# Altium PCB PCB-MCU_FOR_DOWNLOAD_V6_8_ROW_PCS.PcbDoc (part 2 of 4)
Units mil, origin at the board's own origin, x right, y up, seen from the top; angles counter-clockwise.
Board outline not stored, 4 copper layers (Top, GND1, GND2, Bottom), stack 35.4 mil thick; 280 components, 38 nets, 1144 pads, 944 vias.
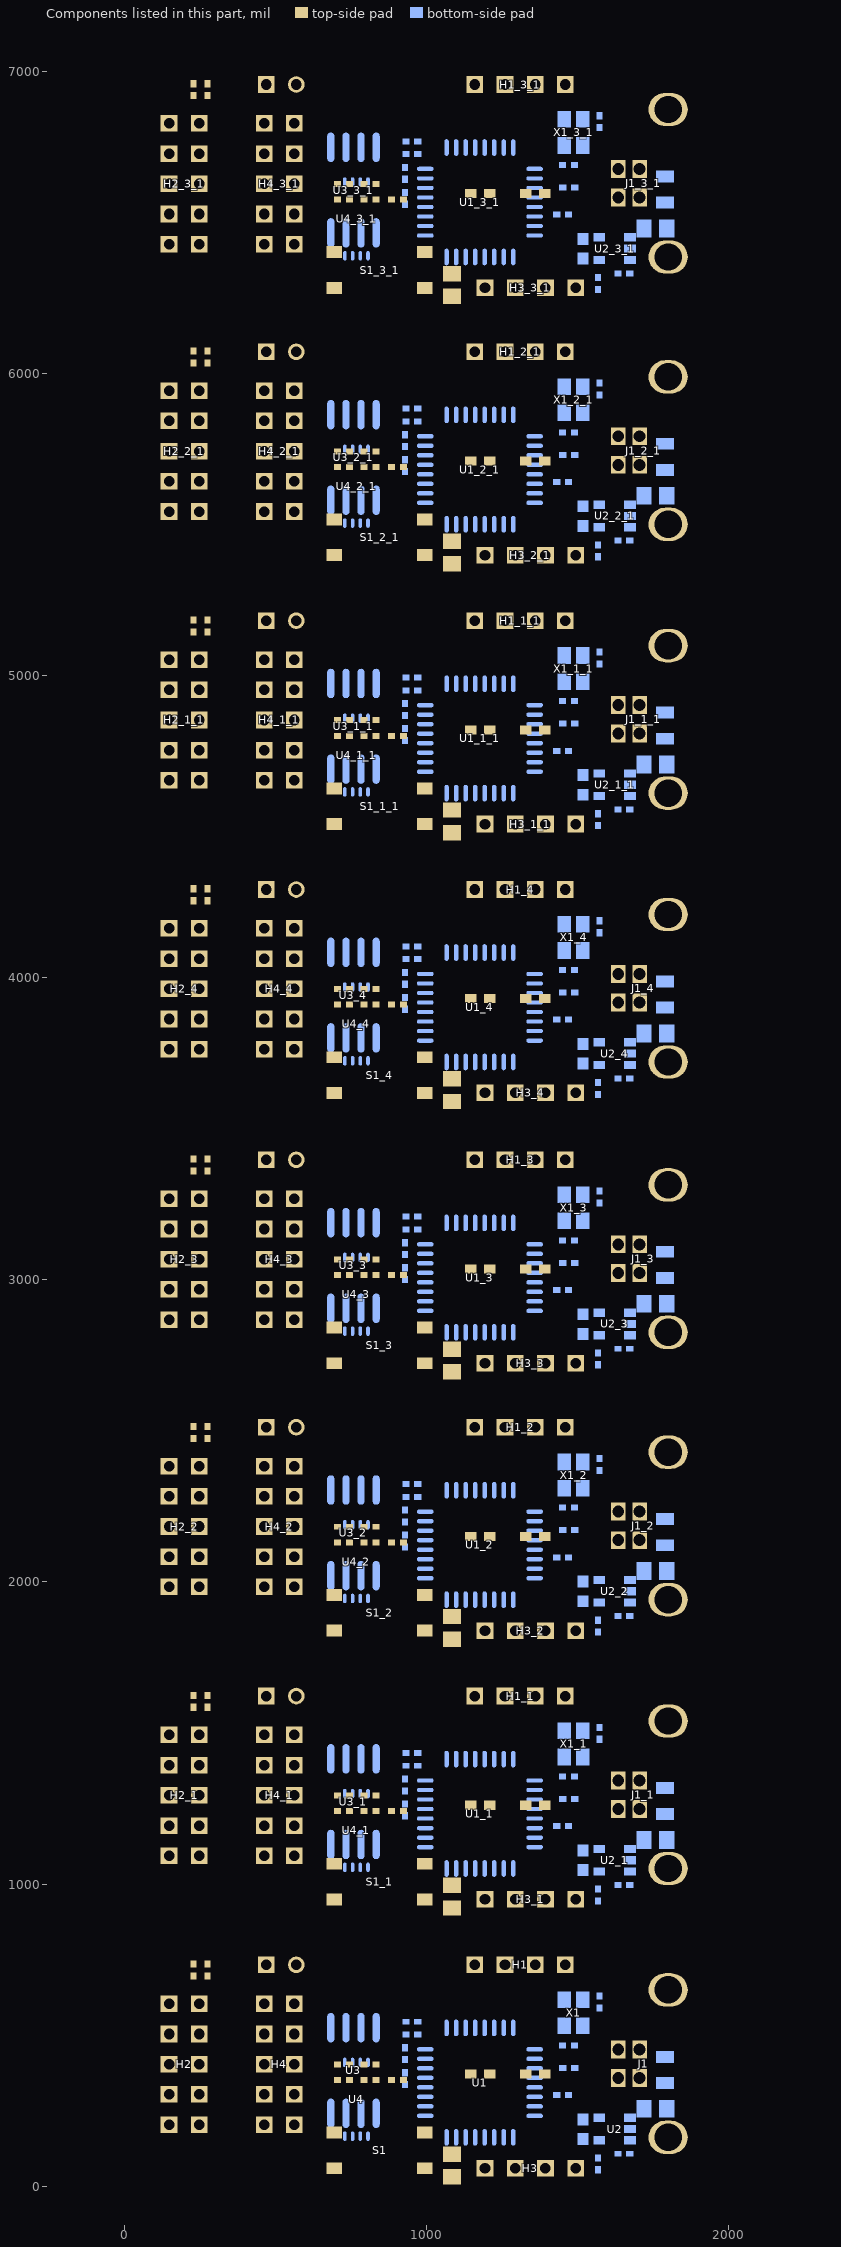
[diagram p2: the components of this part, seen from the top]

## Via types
v1: diameter 16/16/16/16 (per signal layer), hole 8, Top to Bottom, 936 vias
v2: diameter 55/55/55/55 (per signal layer), hole 37, Top to Bottom, 8 vias

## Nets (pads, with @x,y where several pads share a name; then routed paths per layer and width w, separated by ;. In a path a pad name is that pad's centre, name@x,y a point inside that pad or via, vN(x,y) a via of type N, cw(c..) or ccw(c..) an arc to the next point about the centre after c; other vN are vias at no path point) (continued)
copper on no net: | length 208596.2
  Top w7.87: v1(41.34,1641.97) 79.53,1680.16 644.09,1680.16 648.03,1676.22 v1(648.03,1673.07) ; v1(41.34,2531.97) 79.53,2570.16 644.09,2570.16 648.03,2566.22 v1(648.03,2563.07) ; v1(41.34,3416.97) 79.53,3455.16 644.09,3455.16 648.03,3451.22 v1(648.03,3448.07) ; v1(41.34,4311.97) 79.53,4350.16 644.09,4350.16 648.03,4346.22 v1(648.03,4343.07) ; v1(41.34,5201.97) 79.53,5240.16 644.09,5240.16 648.03,5236.22 v1(648.03,5233.07) ; v1(41.34,6091.97) 79.53,6130.16 644.09,6130.16 648.03,6126.22 v1(648.03,6123.07) ; v1(41.34,6976.97) 79.53,7015.16 644.09,7015.16 648.03,7011.22 v1(648.03,7008.07) ; 67.32,1585.28 69.69,1585.28 ; 67.32,2475.28 69.69,2475.28 ; 67.32,3360.28 69.69,3360.28 ; 67.32,4255.28 69.69,4255.28 ; 67.32,5145.28 69.69,5145.28 ; 67.32,6035.28 69.69,6035.28 ; 67.32,6920.28 69.69,6920.28 ; 146.85,1093.54 194.88,1141.57 329.92,1141.57 422.44,1049.06 594.49,1049.06 656.3,1110.87 1048.03,1110.87 v1(1074.41,1084.49) ; 146.85,1193.54 146.85,1194.72 192.52,1240.39 322.34,1240.39 409.45,1153.29 605.02,1153.29 617.32,1140.98 1081.69,1140.98 v1(1127.95,1094.72) ; 146.85,1493.54 149.2,1493.54 203.54,1439.2 203.54,1437.24 292.52,1437.24 314.57,1415.2 314.57,1344.33 425.59,1233.31 597.05,1233.31 674.8,1155.55 1155.71,1155.55 v1(1222.44,1088.82) ; 146.85,1983.54 194.88,2031.57 329.92,2031.57 422.44,1939.06 594.49,1939.06 656.3,2000.87 1048.03,2000.87 v1(1074.41,1974.49) ; 146.85,2083.54 146.85,2084.72 192.52,2130.39 322.34,2130.39 409.45,2043.29 605.02,2043.29 617.32,2030.98 1081.69,2030.98 v1(1127.95,1984.72) ; 146.85,2383.54 149.2,2383.54 203.54,2329.2 203.54,2327.24 292.52,2327.24 314.57,2305.2 314.57,2234.33 425.59,2123.31 597.05,2123.31 674.8,2045.55 1155.71,2045.55 v1(1222.44,1978.82) ; 146.85,2868.54 194.88,2916.57 329.92,2916.57 422.44,2824.06 594.49,2824.06 656.3,2885.87 1048.03,2885.87 v1(1074.41,2859.49) ; 146.85,2968.54 146.85,2969.72 192.52,3015.39 322.34,3015.39 409.45,2928.29 605.02,2928.29 617.32,2915.98 1081.69,2915.98 v1(1127.95,2869.72) ; 146.85,3268.54 149.2,3268.54 203.54,3214.2 203.54,3212.24 292.52,3212.24 314.57,3190.2 314.57,3119.33 425.59,3008.31 597.05,3008.31 674.8,2930.55 1155.71,2930.55 v1(1222.44,2863.82) ; 146.85,3763.54 194.88,3811.57 329.92,3811.57 422.44,3719.06 594.49,3719.06 656.3,3780.87 1048.03,3780.87 v1(1074.41,3754.49) ; 146.85,3863.54 146.85,3864.72 192.52,3910.39 322.34,3910.39 409.45,3823.29 605.02,3823.29 617.32,3810.98 1081.69,3810.98 v1(1127.95,3764.72) ; 146.85,4163.54 149.2,4163.54 203.54,4109.2 203.54,4107.24 292.52,4107.24 314.57,4085.2 314.57,4014.33 425.59,3903.31 597.05,3903.31 674.8,3825.55 1155.71,3825.55 v1(1222.44,3758.82) ; 146.85,4653.54 194.88,4701.57 329.92,4701.57 422.44,4609.06 594.49,4609.06 656.3,4670.87 1048.03,4670.87 v1(1074.41,4644.49) ; 146.85,4753.54 146.85,4754.72 192.52,4800.39 322.34,4800.39 409.45,4713.29 605.02,4713.29 617.32,4700.98 1081.69,4700.98 v1(1127.95,4654.72) ; 146.85,5053.54 149.2,5053.54 203.54,4999.2 203.54,4997.24 292.52,4997.24 314.57,4975.2 314.57,4904.33 425.59,4793.31 597.05,4793.31 674.8,4715.55 1155.71,4715.55 v1(1222.44,4648.82) ; 146.85,5543.54 194.88,5591.57 329.92,5591.57 422.44,5499.06 594.49,5499.06 656.3,5560.87 1048.03,5560.87 v1(1074.41,5534.49) ; 146.85,5643.54 146.85,5644.72 192.52,5690.39 322.34,5690.39 409.45,5603.29 605.02,5603.29 617.32,5590.98 1081.69,5590.98 v1(1127.95,5544.72) ; 146.85,5943.54 149.2,5943.54 203.54,5889.2 203.54,5887.24 292.52,5887.24 314.57,5865.2 314.57,5794.33 425.59,5683.31 597.05,5683.31 674.8,5605.55 1155.71,5605.55 v1(1222.44,5538.82) ; 146.85,6428.54 194.88,6476.57 329.92,6476.57 422.44,6384.06 594.49,6384.06 656.3,6445.87 1048.03,6445.87 v1(1074.41,6419.49) ; 146.85,6528.54 146.85,6529.72 192.52,6575.39 322.34,6575.39 409.45,6488.29 605.02,6488.29 617.32,6475.98 1081.69,6475.98 v1(1127.95,6429.72) ; 146.85,6828.54 149.2,6828.54 203.54,6774.2 203.54,6772.24 292.52,6772.24 314.57,6750.2 314.57,6679.33 425.59,6568.31 597.05,6568.31 674.8,6490.55 1155.71,6490.55 v1(1222.44,6423.82) ; v1(196.85,1054.96) 202.76,1054.96 238.58,1019.13 622.83,1019.13 v1@648.83,1045.13 ; v1(196.85,1944.96) 202.76,1944.96 238.58,1909.13 622.83,1909.13 v1@648.83,1935.13 ; v1(196.85,2829.96) 202.76,2829.96 238.58,2794.13 622.83,2794.13 v1@648.83,2820.13 ; v1(196.85,3724.96) 202.76,3724.96 238.58,3689.13 622.83,3689.13 v1@648.83,3715.13 ; v1(196.85,4614.96) 202.76,4614.96 238.58,4579.13 622.83,4579.13 v1@648.83,4605.13 ; v1(196.85,5504.96) 202.76,5504.96 238.58,5469.13 622.83,5469.13 v1@648.83,5495.13 ; v1(196.85,6389.96) 202.76,6389.96 238.58,6354.13 622.83,6354.13 v1@648.83,6380.13 ; 227.95,1624.65 274.02,1624.65 251.18,1601.81 251.18,1501.02 246.85,1496.69 246.85,1493.54 ; 227.95,2514.65 274.02,2514.65 251.18,2491.81 251.18,2391.02 246.85,2386.69 246.85,2383.54 ; 227.95,3399.65 274.02,3399.65 251.18,3376.81 251.18,3276.02 246.85,3271.69 246.85,3268.54 ; 227.95,4294.65 274.02,4294.65 251.18,4271.81 251.18,4171.02 246.85,4166.69 246.85,4163.54 ; 227.95,5184.65 274.02,5184.65 251.18,5161.81 251.18,5061.02 246.85,5056.69 246.85,5053.54 ; 227.95,6074.65 274.02,6074.65 251.18,6051.81 251.18,5951.02 246.85,5946.69 246.85,5943.54 ; 227.95,6959.65 274.02,6959.65 251.18,6936.81 251.18,6836.02 246.85,6831.69 246.85,6828.54 ; 246.85,1093.54 251.68,1093.54 255.02,1090.2 257.58,1090.2 314.17,1033.6 600.39,1033.6 663.78,1096.99 1025.89,1096.99 1059.65,1063.23 1135.33,1063.23 1156.59,1084.49 1156.99,1084.49 1156.99,1088.33 v1(1159.45,1090.79) ; 246.85,1193.54 327.17,1193.54 327.36,1193.74 385.83,1135.28 599.21,1135.28 609.06,1125.43 1063.78,1125.43 v1(1096.46,1092.76) ; 246.85,1983.54 251.68,1983.54 255.02,1980.2 257.58,1980.2 314.17,1923.6 600.39,1923.6 663.78,1986.99 1025.89,1986.99 1059.65,1953.23 1135.33,1953.23 1156.59,1974.49 1156.99,1974.49 1156.99,1978.33 v1(1159.45,1980.79) ; 246.85,2083.54 327.17,2083.54 327.36,2083.74 385.83,2025.28 599.21,2025.28 609.06,2015.43 1063.78,2015.43 v1(1096.46,1982.76) ; 246.85,2868.54 251.68,2868.54 255.02,2865.2 257.58,2865.2 314.17,2808.6 600.39,2808.6 663.78,2871.99 1025.89,2871.99 1059.65,2838.23 1135.33,2838.23 1156.59,2859.49 1156.99,2859.49 1156.99,2863.33 v1(1159.45,2865.79) ; 246.85,2968.54 327.17,2968.54 327.36,2968.74 385.83,2910.28 599.21,2910.28 609.06,2900.43 1063.78,2900.43 v1(1096.46,2867.76) ; 246.85,3763.54 251.68,3763.54 255.02,3760.2 257.58,3760.2 314.17,3703.6 600.39,3703.6 663.78,3766.99 1025.89,3766.99 1059.65,3733.23 1135.33,3733.23 1156.59,3754.49 1156.99,3754.49 1156.99,3758.33 v1(1159.45,3760.79) ; 246.85,3863.54 327.17,3863.54 327.36,3863.74 385.83,3805.28 599.21,3805.28 609.06,3795.43 1063.78,3795.43 v1(1096.46,3762.76) ; 246.85,4653.54 251.68,4653.54 255.02,4650.2 257.58,4650.2 314.17,4593.6 600.39,4593.6 663.78,4656.99 1025.89,4656.99 1059.65,4623.23 1135.33,4623.23 1156.59,4644.49 1156.99,4644.49 1156.99,4648.33 v1(1159.45,4650.79) ; 246.85,4753.54 327.17,4753.54 327.36,4753.74 385.83,4695.28 599.21,4695.28 609.06,4685.43 1063.78,4685.43 v1(1096.46,4652.76) ; 246.85,5543.54 251.68,5543.54 255.02,5540.2 257.58,5540.2 314.17,5483.6 600.39,5483.6 663.78,5546.99 1025.89,5546.99 1059.65,5513.23 1135.33,5513.23 1156.59,5534.49 1156.99,5534.49 1156.99,5538.33 v1(1159.45,5540.79) ; 246.85,5643.54 327.17,5643.54 327.36,5643.74 385.83,5585.28 599.21,5585.28 609.06,5575.43 1063.78,5575.43 v1(1096.46,5542.76) ; 246.85,6428.54 251.68,6428.54 255.02,6425.2 257.58,6425.2 314.17,6368.6 600.39,6368.6 663.78,6431.99 1025.89,6431.99 1059.65,6398.23 1135.33,6398.23 1156.59,6419.49 1156.99,6419.49 1156.99,6423.33 v1(1159.45,6425.79) ; 246.85,6528.54 327.17,6528.54 327.36,6528.74 385.83,6470.28 599.21,6470.28 609.06,6460.43 1063.78,6460.43 v1(1096.46,6427.76) ; 274.02,1585.28 316.14,1585.28 381.89,1519.53 381.89,1374.25 411.42,1344.72 v1(600.39,1344.72) 701.97,1243.15 701.97,1241.18 701.97,1232.52 706.5,1227.99 ; 274.02,2475.28 316.14,2475.28 381.89,2409.53 381.89,2264.25 411.42,2234.72 v1(600.39,2234.72) 701.97,2133.15 701.97,2131.18 701.97,2122.52 706.5,2117.99 ; 274.02,3360.28 316.14,3360.28 381.89,3294.53 381.89,3149.25 411.42,3119.72 v1(600.39,3119.72) 701.97,3018.15 701.97,3016.18 701.97,3007.52 706.5,3002.99 ; 274.02,4255.28 316.14,4255.28 381.89,4189.53 381.89,4044.25 411.42,4014.72 v1(600.39,4014.72) 701.97,3913.15 701.97,3911.18 701.97,3902.52 706.5,3897.99 ; 274.02,5145.28 316.14,5145.28 381.89,5079.53 381.89,4934.25 411.42,4904.72 v1(600.39,4904.72) 701.97,4803.15 701.97,4801.18 701.97,4792.52 706.5,4787.99 ; 274.02,6035.28 316.14,6035.28 381.89,5969.53 381.89,5824.25 411.42,5794.72 v1(600.39,5794.72) 701.97,5693.15 701.97,5691.18 701.97,5682.52 706.5,5677.99 ; 274.02,6920.28 316.14,6920.28 381.89,6854.53 381.89,6709.25 411.42,6679.72 v1(600.39,6679.72) 701.97,6578.15 701.97,6576.18 701.97,6567.52 706.5,6562.99 ; 461.81,1493.54 460.63,1493.54 458.27,1491.18 458.86,1490.59 497.24,1452.2 759.45,1452.2 826.77,1384.88 869.29,1384.88 v1(872.05,1382.13) ; 461.81,2383.54 460.63,2383.54 458.27,2381.18 458.86,2380.59 497.24,2342.2 759.45,2342.2 826.77,2274.88 869.29,2274.88 v1(872.05,2272.13) ; 461.81,3268.54 460.63,3268.54 458.27,3266.18 458.86,3265.59 497.24,3227.2 759.45,3227.2 826.77,3159.88 869.29,3159.88 v1(872.05,3157.13) ; 461.81,4163.54 460.63,4163.54 458.27,4161.18 458.86,4160.59 497.24,4122.2 759.45,4122.2 826.77,4054.88 869.29,4054.88 v1(872.05,4052.13) ; 461.81,5053.54 460.63,5053.54 458.27,5051.18 458.86,5050.59 497.24,5012.2 759.45,5012.2 826.77,4944.88 869.29,4944.88 v1(872.05,4942.13) ; 461.81,5943.54 460.63,5943.54 458.27,5941.18 458.86,5940.59 497.24,5902.2 759.45,5902.2 826.77,5834.88 869.29,5834.88 v1(872.05,5832.13) ; 461.81,6828.54 460.63,6828.54 458.27,6826.18 458.86,6825.59 497.24,6787.2 759.45,6787.2 826.77,6719.88 869.29,6719.88 v1(872.05,6717.13) ; v1(692.91,1187.24) 693.31,1187.24 710.63,1169.92 1176.77,1169.92 v1(1185.04,1161.65) ; v1(692.91,1360.47) v1(1149.61,1360.47) ; v1(692.91,2077.24) 693.31,2077.24 710.63,2059.92 1176.77,2059.92 v1(1185.04,2051.65) ; v1(692.91,2250.47) v1(1149.61,2250.47) ; v1(692.91,2962.24) 693.31,2962.24 710.63,2944.92 1176.77,2944.92 v1(1185.04,2936.65) ; v1(692.91,3135.47) v1(1149.61,3135.47) ; v1(692.91,3857.24) 693.31,3857.24 710.63,3839.92 1176.77,3839.92 v1(1185.04,3831.65) ; v1(692.91,4030.47) v1(1149.61,4030.47) ; v1(692.91,4747.24) 693.31,4747.24 710.63,4729.92 1176.77,4729.92 v1(1185.04,4721.65) ; v1(692.91,4920.47) v1(1149.61,4920.47) ; v1(692.91,5637.24) 693.31,5637.24 710.63,5619.92 1176.77,5619.92 v1(1185.04,5611.65) ; v1(692.91,5810.47) v1(1149.61,5810.47) ; v1(692.91,6522.24) 693.31,6522.24 710.63,6504.92 1176.77,6504.92 v1(1185.04,6496.65) ; v1(692.91,6695.47) v1(1149.61,6695.47) ; 704.72,1241.18 706.5,1239.41 706.5,1227.99 ; 704.72,1292.76 704.72,1320.31 725.2,1340.79 874.8,1340.79 ; 704.72,2131.18 706.5,2129.41 706.5,2117.99 ; 704.72,2182.76 704.72,2210.31 725.2,2230.79 874.8,2230.79 ; 704.72,3016.18 706.5,3014.41 706.5,3002.99 ; 704.72,3067.76 704.72,3095.31 725.2,3115.79 874.8,3115.79 ; 704.72,3911.18 706.5,3909.41 706.5,3897.99 ; 704.72,3962.76 704.72,3990.31 725.2,4010.79 874.8,4010.79 ; 704.72,4801.18 706.5,4799.41 706.5,4787.99 ; 704.72,4852.76 704.72,4880.31 725.2,4900.79 874.8,4900.79 ; 704.72,5691.18 706.5,5689.41 706.5,5677.99 ; 704.72,5742.76 704.72,5770.31 725.2,5790.79 874.8,5790.79 ; 704.72,6576.18 706.5,6574.41 706.5,6562.99 ; 704.72,6627.76 704.72,6655.31 725.2,6675.79 874.8,6675.79 ; 744.09,1241.18 744.09,1292.76 744.09,1313.62 751.18,1320.71 753.54,1320.71 v1(753.94,1321.1) ; 744.09,2131.18 744.09,2182.76 744.09,2203.62 751.18,2210.71 753.54,2210.71 v1(753.94,2211.1) ; 744.09,3016.18 744.09,3067.76 744.09,3088.62 751.18,3095.71 753.54,3095.71 v1(753.94,3096.1) ; 744.09,3911.18 744.09,3962.76 744.09,3983.62 751.18,3990.71 753.54,3990.71 v1(753.94,3991.1) ; 744.09,4801.18 744.09,4852.76 744.09,4873.62 751.18,4880.71 753.54,4880.71 v1(753.94,4881.1) ; 744.09,5691.18 744.09,5742.76 744.09,5763.62 751.18,5770.71 753.54,5770.71 v1(753.94,5771.1) ; 744.09,6576.18 744.09,6627.76 744.09,6648.62 751.18,6655.71 753.54,6655.71 v1(753.94,6656.1) ; v1(783.46,1321.1) 803.15,1321.1 831.5,1292.76 ; v1(783.46,2211.1) 803.15,2211.1 831.5,2182.76 ; v1(783.46,3096.1) 803.15,3096.1 831.5,3067.76 ; v1(783.46,3991.1) 803.15,3991.1 831.5,3962.76 ; v1(783.46,4881.1) 803.15,4881.1 831.5,4852.76 ; v1(783.46,5771.1) 803.15,5771.1 831.5,5742.76 ; v1(783.46,6656.1) 803.15,6656.1 831.5,6627.76 ; v1(791.34,1210.87) 795.67,1206.54 795.67,1206.34 1225.2,1206.34 1261.42,1242.56 1261.42,1295.12 v1(1309.06,1342.76) ; v1(791.34,2100.87) 795.67,2096.54 795.67,2096.34 1225.2,2096.34 1261.42,2132.56 1261.42,2185.12 v1(1309.06,2232.76) ; v1(791.34,2985.87) 795.67,2981.54 795.67,2981.34 1225.2,2981.34 1261.42,3017.56 1261.42,3070.12 v1(1309.06,3117.76) ; v1(791.34,3880.87) 795.67,3876.54 795.67,3876.34 1225.2,3876.34 1261.42,3912.56 1261.42,3965.12 v1(1309.06,4012.76) ; v1(791.34,4770.87) 795.67,4766.54 795.67,4766.34 1225.2,4766.34 1261.42,4802.56 1261.42,4855.12 v1(1309.06,4902.76) ; v1(791.34,5660.87) 795.67,5656.54 795.67,5656.34 1225.2,5656.34 1261.42,5692.56 1261.42,5745.12 v1(1309.06,5792.76) ; v1(791.34,6545.87) 795.67,6541.54 795.67,6541.34 1225.2,6541.34 1261.42,6577.56 1261.42,6630.12 v1(1309.06,6677.76) ; 792.13,1241.18 792.13,1242.76 828.74,1279.37 828.74,1291.22 829.12,1291.59 829.12,1291.95 ; 792.13,1292.76 790.55,1292.76 767.5,1269.7 767.5,1240.79 767.13,1191.57 766.54,1188.43 ; 792.13,2131.18 792.13,2132.76 828.74,2169.37 828.74,2181.22 829.12,2181.59 829.12,2181.95 ; 792.13,2182.76 790.55,2182.76 767.5,2159.7 767.5,2130.79 767.13,2081.57 766.54,2078.43 ; 792.13,3016.18 792.13,3017.76 828.74,3054.37 828.74,3066.22 829.12,3066.59 829.12,3066.95 ; 792.13,3067.76 790.55,3067.76 767.5,3044.7 767.5,3015.79 767.13,2966.57 766.54,2963.43 ; 792.13,3911.18 792.13,3912.76 828.74,3949.37 828.74,3961.22 829.12,3961.59 829.12,3961.95 ; 792.13,3962.76 790.55,3962.76 767.5,3939.7 767.5,3910.79 767.13,3861.57 766.54,3858.43 ; 792.13,4801.18 792.13,4802.76 828.74,4839.37 828.74,4851.22 829.12,4851.59 829.12,4851.95 ; 792.13,4852.76 790.55,4852.76 767.5,4829.7 767.5,4800.79 767.13,4751.57 766.54,4748.43 ; 792.13,5691.18 792.13,5692.76 828.74,5729.37 828.74,5741.22 829.12,5741.59 829.12,5741.95 ; 792.13,5742.76 790.55,5742.76 767.5,5719.7 767.5,5690.79 767.13,5641.57 766.54,5638.43 ; 792.13,6576.18 792.13,6577.76 828.74,6614.37 828.74,6626.22 829.12,6626.59 829.12,6626.95 ; 792.13,6627.76 790.55,6627.76 767.5,6604.7 767.5,6575.79 767.13,6526.57 766.54,6523.43 ; 831.5,1241.18 832.28,1240.39 832.28,1238.03 838.39,1231.93 838.39,1230.75 v1(844.49,1224.65) ; 831.5,2131.18 832.28,2130.39 832.28,2128.03 838.39,2121.93 838.39,2120.75 v1(844.49,2114.65) ; 831.5,3016.18 832.28,3015.39 832.28,3013.03 838.39,3006.93 838.39,3005.75 v1(844.49,2999.65) ; 831.5,3911.18 832.28,3910.39 832.28,3908.03 838.39,3901.93 838.39,3900.75 v1(844.49,3894.65) ; 831.5,4801.18 832.28,4800.39 832.28,4798.03 838.39,4791.93 838.39,4790.75 v1(844.49,4784.65) ; 831.5,5691.18 832.28,5690.39 832.28,5688.03 838.39,5681.93 838.39,5680.75 v1(844.49,5674.65) ; 831.5,6576.18 832.28,6575.39 832.28,6573.03 838.39,6566.93 838.39,6565.75 v1(844.49,6559.65) ; 874.8,1241.57 874.8,1340.79 ; 874.8,2131.57 874.8,2230.79 ; 874.8,3016.57 874.8,3115.79 ; 874.8,3911.57 874.8,4010.79 ; 874.8,4801.57 874.8,4900.79 ; 874.8,5691.57 874.8,5790.79 ; 874.8,6576.57 874.8,6675.79 ; v1(893.7,1269.92) 922.44,1241.18 ; v1(893.7,2159.92) 922.44,2131.18 ; v1(893.7,3044.92) 922.44,3016.18 ; v1(893.7,3939.92) 922.44,3911.18 ; v1(893.7,4829.92) 922.44,4801.18 ; v1(893.7,5719.92) 922.44,5691.18 ; v1(893.7,6604.92) 922.44,6576.18 ; v1(944.88,1069.13) 991.34,1069.13 993.31,1067.17 ; v1(944.88,1959.13) 991.34,1959.13 993.31,1957.17 ; v1(944.88,2844.13) 991.34,2844.13 993.31,2842.17 ; v1(944.88,3739.13) 991.34,3739.13 993.31,3737.17 ; v1(944.88,4629.13) 991.34,4629.13 993.31,4627.17 ; v1(944.88,5519.13) 991.34,5519.13 993.31,5517.17 ; v1(944.88,6404.13) 991.34,6404.13 993.31,6402.17 ; v1(948.82,1265.98) 1143.31,1265.98 1146.17,1263.13 1146.17,1260.87 ; v1(948.82,2155.98) 1143.31,2155.98 1146.17,2153.13 1146.17,2150.87 ; v1(948.82,3040.98) 1143.31,3040.98 1146.17,3038.13 1146.17,3035.87 ; v1(948.82,3935.98) 1143.31,3935.98 1146.17,3933.13 1146.17,3930.87 ; v1(948.82,4825.98) 1143.31,4825.98 1146.17,4823.13 1146.17,4820.87 ; v1(948.82,5715.98) 1143.31,5715.98 1146.17,5713.13 1146.17,5710.87 ; v1(948.82,6600.98) 1143.31,6600.98 1146.17,6598.13 1146.17,6595.87 ; v1(1191.73,1378.98) 1192.52,1378.19 1192.52,1372.68 1160.63,1340.79 874.8,1340.79 ; v1(1191.73,2268.98) 1192.52,2268.19 1192.52,2262.68 1160.63,2230.79 874.8,2230.79 ; v1(1191.73,3153.98) 1192.52,3153.19 1192.52,3147.68 1160.63,3115.79 874.8,3115.79 ; v1(1191.73,4048.98) 1192.52,4048.19 1192.52,4042.68 1160.63,4010.79 874.8,4010.79 ; v1(1191.73,4938.98) 1192.52,4938.19 1192.52,4932.68 1160.63,4900.79 874.8,4900.79 ; v1(1191.73,5828.98) 1192.52,5828.19 1192.52,5822.68 1160.63,5790.79 874.8,5790.79 ; v1(1191.73,6713.98) 1192.52,6713.19 1192.52,6707.68 1160.63,6675.79 874.8,6675.79 ; v1(1222.44,1122.28) 1223.62,1123.46 1283.86,1123.46 1309.65,1097.68 1583.27,1097.68 1639.76,1041.18 1640.16,1041.57 v1(1702.76,1041.57) ; v1(1222.44,2012.28) 1223.62,2013.46 1283.86,2013.46 1309.65,1987.68 1583.27,1987.68 1639.76,1931.18 1640.16,1931.57 v1(1702.76,1931.57) ; v1(1222.44,2897.28) 1223.62,2898.46 1283.86,2898.46 1309.65,2872.68 1583.27,2872.68 1639.76,2816.18 1640.16,2816.57 v1(1702.76,2816.57) ; v1(1222.44,3792.28) 1223.62,3793.46 1283.86,3793.46 1309.65,3767.68 1583.27,3767.68 1639.76,3711.18 1640.16,3711.57 v1(1702.76,3711.57) ; v1(1222.44,4682.28) 1223.62,4683.46 1283.86,4683.46 1309.65,4657.68 1583.27,4657.68 1639.76,4601.18 1640.16,4601.57 v1(1702.76,4601.57) ; v1(1222.44,5572.28) 1223.62,5573.46 1283.86,5573.46 1309.65,5547.68 1583.27,5547.68 1639.76,5491.18 1640.16,5491.57 v1(1702.76,5491.57) ; v1(1222.44,6457.28) 1223.62,6458.46 1283.86,6458.46 1309.65,6432.68 1583.27,6432.68 1639.76,6376.18 1640.16,6376.57 v1(1702.76,6376.57) ; v1(1263.78,1096.69) 1263.39,1082.13 1218.9,1037.64 v1(944.88,1037.64) 660.24,1037.64 649.21,1044.89 v1@648.83,1045.13 ; v1(1263.78,1986.69) 1263.39,1972.13 1218.9,1927.64 v1(944.88,1927.64) 660.24,1927.64 649.21,1934.89 v1@648.83,1935.13 ; v1(1263.78,2871.69) 1263.39,2857.13 1218.9,2812.64 v1(944.88,2812.64) 660.24,2812.64 649.21,2819.89 v1@648.83,2820.13 ; v1(1263.78,3766.69) 1263.39,3752.13 1218.9,3707.64 v1(944.88,3707.64) 660.24,3707.64 649.21,3714.89 v1@648.83,3715.13 ; v1(1263.78,4656.69) 1263.39,4642.13 1218.9,4597.64 v1(944.88,4597.64) 660.24,4597.64 649.21,4604.89 v1@648.83,4605.13 ; v1(1263.78,5546.69) 1263.39,5532.13 1218.9,5487.64 v1(944.88,5487.64) 660.24,5487.64 649.21,5494.89 v1@648.83,5495.13 ; v1(1263.78,6431.69) 1263.39,6417.13 1218.9,6372.64 v1(944.88,6372.64) 660.24,6372.64 649.21,6379.89 v1@648.83,6380.13 ; v1(1311.02,1311.26) 1309.45,1312.83 1305.12,1312.83 1301.77,1309.49 1300.98,1309.49 1280.51,1289.02 1280.51,1216.57 1252.36,1188.43 766.54,1188.43 ; v1(1311.02,2201.26) 1309.45,2202.83 1305.12,2202.83 1301.77,2199.49 1300.98,2199.49 1280.51,2179.02 1280.51,2106.57 1252.36,2078.43 766.54,2078.43 ; v1(1311.02,3086.26) 1309.45,3087.83 1305.12,3087.83 1301.77,3084.49 1300.98,3084.49 1280.51,3064.02 1280.51,2991.57 1252.36,2963.43 766.54,2963.43 ; v1(1311.02,3981.26) 1309.45,3982.83 1305.12,3982.83 1301.77,3979.49 1300.98,3979.49 1280.51,3959.02 1280.51,3886.57 1252.36,3858.43 766.54,3858.43 ; v1(1311.02,4871.26) 1309.45,4872.83 1305.12,4872.83 1301.77,4869.49 1300.98,4869.49 1280.51,4849.02 1280.51,4776.57 1252.36,4748.43 766.54,4748.43 ; v1(1311.02,5761.26) 1309.45,5762.83 1305.12,5762.83 1301.77,5759.49 1300.98,5759.49 1280.51,5739.02 1280.51,5666.57 1252.36,5638.43 766.54,5638.43 ; v1(1311.02,6646.26) 1309.45,6647.83 1305.12,6647.83 1301.77,6644.49 1300.98,6644.49 1280.51,6624.02 1280.51,6551.57 1252.36,6523.43 766.54,6523.43 ; v1(1322.83,1286.06) 1327.27,1281.63 1327.27,1260.87 ; v1(1322.83,2176.06) 1327.27,2171.63 1327.27,2150.87 ; v1(1322.83,3061.06) 1327.27,3056.63 1327.27,3035.87 ; v1(1322.83,3956.06) 1327.27,3951.63 1327.27,3930.87 ; v1(1322.83,4846.06) 1327.27,4841.63 1327.27,4820.87 ; v1(1322.83,5736.06) 1327.27,5731.63 1327.27,5710.87 ; v1(1322.83,6621.06) 1327.27,6616.63 1327.27,6595.87 ; 1390.26,1260.87 1390.26,1262.44 1405.91,1262.44 v1(1425.2,1281.73) ; 1390.26,2150.87 1390.26,2152.44 1405.91,2152.44 v1(1425.2,2171.73) ; 1390.26,3035.87 1390.26,3037.44 1405.91,3037.44 v1(1425.2,3056.73) ; 1390.26,3930.87 1390.26,3932.44 1405.91,3932.44 v1(1425.2,3951.73) ; 1390.26,4820.87 1390.26,4822.44 1405.91,4822.44 v1(1425.2,4841.73) ; 1390.26,5710.87 1390.26,5712.44 1405.91,5712.44 v1(1425.2,5731.73) ; 1390.26,6595.87 1390.26,6597.44 1405.91,6597.44 v1(1425.2,6616.73) ; v1@648.83,1045.13 v1(650.39,1046.69) 646.46,1046.69 v1@648.83,1045.13 ; v1@648.83,1935.13 v1(650.39,1936.69) 646.46,1936.69 v1@648.83,1935.13 ; v1@648.83,2820.13 v1(650.39,2821.69) 646.46,2821.69 v1@648.83,2820.13 ; v1@648.83,3715.13 v1(650.39,3716.69) 646.46,3716.69 v1@648.83,3715.13 ; v1@648.83,4605.13 646.46,4606.69 v1(650.39,4606.69) v1@648.83,4605.13 ; v1@648.83,5495.13 646.46,5496.69 v1(650.39,5496.69) v1@648.83,5495.13 ; v1@648.83,6380.13 646.46,6381.69 v1(650.39,6381.69) v1@648.83,6380.13 ; 706.5,1227.99 743.5,1190.98 746.06,1188.43 766.54,1188.43 ; 706.5,2117.99 743.5,2080.98 746.06,2078.43 766.54,2078.43 ; 706.5,3002.99 743.5,2965.98 746.06,2963.43 766.54,2963.43 ; 706.5,3897.99 743.5,3860.98 746.06,3858.43 766.54,3858.43 ; 706.5,4787.99 743.5,4750.98 746.06,4748.43 766.54,4748.43 ; 706.5,5677.99 743.5,5640.98 746.06,5638.43 766.54,5638.43 ; 706.5,6562.99 743.5,6525.98 746.06,6523.43 766.54,6523.43
  Top w11.81: 69.69,1585.28 227.95,1585.28 ; 69.69,2475.28 227.95,2475.28 ; 69.69,3360.28 227.95,3360.28 ; 69.69,4255.28 227.95,4255.28 ; 69.69,5145.28 227.95,5145.28 ; 69.69,6035.28 227.95,6035.28 ; 69.69,6920.28 227.95,6920.28
  Top w19.68: 694.09,1067.17 944.88,1067.17 993.31,1067.17 ; 694.09,1957.17 944.88,1957.17 993.31,1957.17 ; 694.09,2842.17 944.88,2842.17 993.31,2842.17 ; 694.09,3737.17 944.88,3737.17 993.31,3737.17 ; 694.09,4627.17 944.88,4627.17 993.31,4627.17 ; 694.09,5517.17 944.88,5517.17 993.31,5517.17 ; 694.09,6402.17 944.88,6402.17 993.31,6402.17 ; 1083.07,920.63 1083.94,921.5 v1(1137.8,921.5) ; 1083.07,1810.63 1083.94,1811.5 v1(1137.8,1811.5) ; 1083.07,2695.63 1083.94,2696.5 v1(1137.8,2696.5) ; 1083.07,3590.63 1083.94,3591.5 v1(1137.8,3591.5) ; 1083.07,4480.63 1083.94,4481.5 v1(1137.8,4481.5) ; 1083.07,5370.63 1083.94,5371.5 v1(1137.8,5371.5) ; 1083.07,6255.63 1083.94,6256.5 v1(1137.8,6256.5)
  Top w22.05: v1(1035.43,909.69) 1072.13,909.69 1078.39,915.95 1083.07,920.63 ; v1(1035.43,1799.69) 1072.13,1799.69 1078.39,1805.95 1083.07,1810.63 ; v1(1035.43,2684.69) 1072.13,2684.69 1078.39,2690.95 1083.07,2695.63 ; v1(1035.43,3579.69) 1072.13,3579.69 1078.39,3585.95 1083.07,3590.63 ; v1(1035.43,4469.69) 1072.13,4469.69 1078.39,4475.95 1083.07,4480.63 ; v1(1035.43,5359.69) 1072.13,5359.69 1078.39,5365.95 1083.07,5370.63 ; v1(1035.43,6244.69) 1072.13,6244.69 1078.39,6250.95 1083.07,6255.63
  Top w23.62: 246.85,1393.54 246,1392.69 246,1386.61 205.51,1346.12 205.51,1344.72 67.32,1344.72 ; 246.85,2283.54 246,2282.69 246,2276.61 205.51,2236.12 205.51,2234.72 67.32,2234.72 ; 246.85,3168.54 246,3167.69 246,3161.61 205.51,3121.12 205.51,3119.72 67.32,3119.72 ; 246.85,4063.54 246,4062.69 246,4056.61 205.51,4016.12 205.51,4014.72 67.32,4014.72 ; 246.85,4953.54 246,4952.69 246,4946.61 205.51,4906.12 205.51,4904.72 67.32,4904.72 ; 246.85,5843.54 246,5842.69 246,5836.61 205.51,5796.12 205.51,5794.72 67.32,5794.72 ; 246.85,6728.54 246,6727.69 246,6721.61 205.51,6681.12 205.51,6679.72 67.32,6679.72 ; 468.11,1622.28 468.11,1623.46 436.61,1654.96 125.2,1654.96 67.32,1597.09 67.32,1585.28 67.32,1344.72 ; 468.11,2512.28 468.11,2513.46 436.61,2544.96 125.2,2544.96 67.32,2487.09 67.32,2475.28 67.32,2234.72 ; 468.11,3397.28 468.11,3398.46 436.61,3429.96 125.2,3429.96 67.32,3372.09 67.32,3360.28 67.32,3119.72 ; 468.11,4292.28 468.11,4293.46 436.61,4324.96 125.2,4324.96 67.32,4267.09 67.32,4255.28 67.32,4014.72 ; 468.11,5182.28 468.11,5183.46 436.61,5214.96 125.2,5214.96 67.32,5157.09 67.32,5145.28 67.32,4904.72 ; 468.11,6072.28 468.11,6073.46 436.61,6104.96 125.2,6104.96 67.32,6047.09 67.32,6035.28 67.32,5794.72 ; 468.11,6957.28 468.11,6958.46 436.61,6989.96 125.2,6989.96 67.32,6932.09 67.32,6920.28 67.32,6679.72 ; 568.11,1622.28 589.17,1601.22 589.57,1601.22 605.12,1585.67 1066.54,1585.67 1231.1,1421.1 1231.1,1384.88 ; 568.11,2512.28 589.17,2491.22 589.57,2491.22 605.12,2475.67 1066.54,2475.67 1231.1,2311.1 1231.1,2274.88 ; 568.11,3397.28 589.17,3376.22 589.57,3376.22 605.12,3360.67 1066.54,3360.67 1231.1,3196.1 1231.1,3159.88 ; 568.11,4292.28 589.17,4271.22 589.57,4271.22 605.12,4255.67 1066.54,4255.67 1231.1,4091.1 1231.1,4054.88 ; 568.11,5182.28 589.17,5161.22 589.57,5161.22 605.12,5145.67 1066.54,5145.67 1231.1,4981.1 1231.1,4944.88 ; 568.11,6072.28 589.17,6051.22 589.57,6051.22 605.12,6035.67 1066.54,6035.67 1231.1,5871.1 1231.1,5834.88 ; 568.11,6957.28 589.17,6936.22 589.57,6936.22 605.12,6920.67 1066.54,6920.67 1231.1,6756.1 1231.1,6719.88 ; 1083.07,995.59 1074.49,1004.17 662.2,1004.17 639.37,981.34 125.2,981.34 67.32,1039.21 67.32,1344.72 ; 1083.07,1885.59 1074.49,1894.17 662.2,1894.17 639.37,1871.34 125.2,1871.34 67.32,1929.21 67.32,2234.72 ; 1083.07,2770.59 1074.49,2779.17 662.2,2779.17 639.37,2756.34 125.2,2756.34 67.32,2814.21 67.32,3119.72 ; 1083.07,3665.59 1074.49,3674.17 662.2,3674.17 639.37,3651.34 125.2,3651.34 67.32,3709.21 67.32,4014.72 ; 1083.07,4555.59 1074.49,4564.17 662.2,4564.17 639.37,4541.34 125.2,4541.34 67.32,4599.21 67.32,4904.72 ; 1083.07,5445.59 1074.49,5454.17 662.2,5454.17 639.37,5431.34 125.2,5431.34 67.32,5489.21 67.32,5794.72 ; 1083.07,6330.59 1074.49,6339.17 662.2,6339.17 639.37,6316.34 125.2,6316.34 67.32,6374.21 67.32,6679.72 ; 1209.16,1260.87 1231.1,1282.81 1231.1,1384.88 ; 1209.16,2150.87 1231.1,2172.81 1231.1,2274.88 ; 1209.16,3035.87 1231.1,3057.81 1231.1,3159.88 ; 1209.16,3930.87 1231.1,3952.81 1231.1,4054.88 ; 1209.16,4820.87 1231.1,4842.81 1231.1,4944.88 ; 1209.16,5710.87 1231.1,5732.81 1231.1,5834.88 ; 1209.16,6595.87 1231.1,6617.81 1231.1,6719.88 ; v1(1397.64,1185.28) 1490.94,1278.58 v1@1518.9,1278.58 ; v1(1397.64,2075.28) 1490.94,2168.58 v1@1518.9,2168.58 ; v1(1397.64,2960.28) 1490.94,3053.58 v1@1518.9,3053.58 ; v1(1397.64,3855.28) 1490.94,3948.58 v1@1518.9,3948.58 ; v1(1397.64,4745.28) 1490.94,4838.58 v1@1518.9,4838.58 ; v1(1397.64,5635.28) 1490.94,5728.58 v1@1518.9,5728.58 ; v1(1397.64,6520.28) 1490.94,6613.58 v1@1518.9,6613.58 ; v1(1519.69,1277.8) v1@1518.9,1278.58 ; v1(1519.69,2167.8) v1@1518.9,2168.58 ; v1(1519.69,3052.8) v1@1518.9,3053.58 ; v1(1519.69,3947.8) v1@1518.9,3948.58 ; v1(1519.69,4837.8) v1@1518.9,4838.58 ; v1(1519.69,5727.8) v1@1518.9,5728.58 ; v1(1519.69,6612.8) v1@1518.9,6613.58 ; 1231.1,1384.88 1412.6,1384.88 v1@1518.9,1278.58 ; 1231.1,2274.88 1412.6,2274.88 v1@1518.9,2168.58 ; 1231.1,3159.88 1412.6,3159.88 v1@1518.9,3053.58 ; 1231.1,4054.88 1412.6,4054.88 v1@1518.9,3948.58 ; 1231.1,4944.88 1412.6,4944.88 v1@1518.9,4838.58 ; 1231.1,5834.88 1412.6,5834.88 v1@1518.9,5728.58 ; 1231.1,6719.88 1412.6,6719.88 v1@1518.9,6613.58
  Top w31.5: 1083.07,995.59 1095.2,1007.72 1283.86,1007.72 1333.46,1056.54 v2(1348.03,1056.54) ; 1083.07,1885.59 1095.2,1897.72 1283.86,1897.72 1333.46,1946.54 v2(1348.03,1946.54) ; 1083.07,2770.59 1095.2,2782.72 1283.86,2782.72 1333.46,2831.54 v2(1348.03,2831.54) ; 1083.07,3665.59 1095.2,3677.72 1283.86,3677.72 1333.46,3726.54 v2(1348.03,3726.54) ; 1083.07,4555.59 1095.2,4567.72 1283.86,4567.72 1333.46,4616.54 v2(1348.03,4616.54) ; 1083.07,5445.59 1095.2,5457.72 1283.86,5457.72 1333.46,5506.54 v2(1348.03,5506.54) ; 1083.07,6330.59 1095.2,6342.72 1283.86,6342.72 1333.46,6391.54 v2(1348.03,6391.54)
